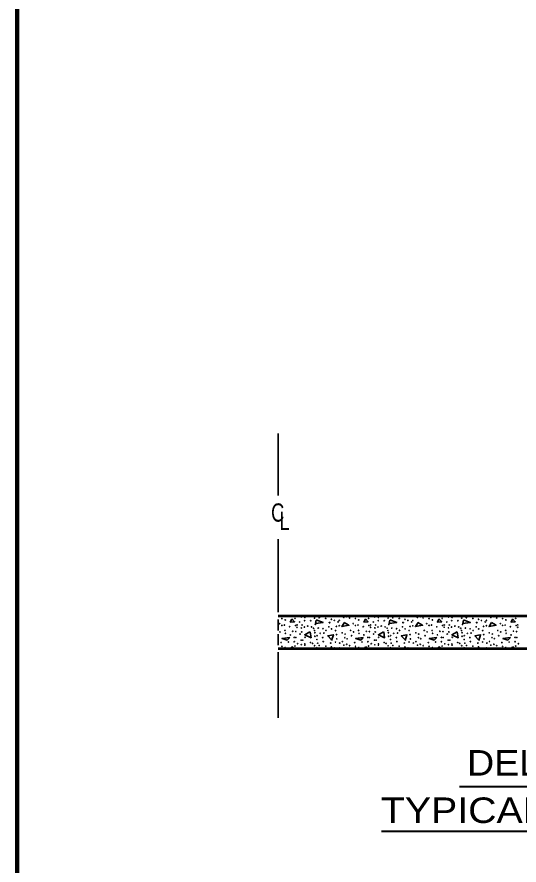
# Model space of a CAD drawing. Extents: x -89 to 766, y -60 to 484.
# Drawn here: x -31.9 to 50.6, y 91.5 to 231 of the extents above; entities that cross this region are included whole.
import ezdxf
from ezdxf.enums import TextEntityAlignment as Align

# ---------------------------------------------------------------- set-up
doc = ezdxf.new("R2010")
doc.units = 0
doc.header["$LTSCALE"] = 1.1
doc.layers.add('1', color=7, linetype='Continuous', lineweight=35)

msp = doc.modelspace()

# ---------------------------------------------------------------- linework, layer by layer
at = {"layer": '1'}
for p, q in [((11.028, 152.314), (11.028, 162.514)), ((11.028, 133.114), (11.028, 145.114)), ((11.028, 131.914), (11.028, 130.114)), ((11.028, 129.514), (11.028, 127.714)), ((13.138, 127.114), (13.287, 127.413)), ((13.287, 127.461), (13.617, 127.114)), ((17.291, 127.114), (17.319, 127.245)), ((17.319, 127.293), (17.763, 127.114)), ((25.234, 127.114), (25.383, 127.413)), ((25.383, 127.461), (25.713, 127.114)), ((29.387, 127.114), (29.415, 127.245)), ((29.415, 127.293), (29.859, 127.114)), ((37.33, 127.114), (37.479, 127.413)), ((37.479, 127.461), (37.809, 127.114)), ((41.483, 127.114), (41.511, 127.245)), ((41.511, 127.293), (41.955, 127.114)), ((49.426, 127.114), (49.575, 127.413)), ((49.575, 127.461), (49.905, 127.114)), ((11.028, 126.514), (11.028, 115.714))]:
    msp.add_line(p, q, dxfattribs=at)
at = {"layer": '1', "lineweight": 53}
for p, q in [((11.028, 132.514), (96.828, 132.514)), ((96.828, 127.114), (11.028, 127.114))]:
    msp.add_line(p, q, dxfattribs=at)
at = {"layer": '1', "lineweight": 40}
for p, q in [((40.868, 104.433), (122.541, 104.433)), ((28.02, 97.103), (136.478, 97.103))]:
    msp.add_line(p, q, dxfattribs=at)
at = {"layer": '1', "lineweight": 158}
msp.add_lwpolyline([(759.817, 478.083), (-31.883, 477.983), (-31.783, -48.017)], dxfattribs=at)
at = {"layer": '1'}
for points in [[(13.287, 132.021), (13.743, 131.541), (13.047, 131.493), (13.287, 131.973)], [(17.319, 131.853), (18.447, 131.397), (17.199, 131.253), (17.319, 131.805)], [(21.903, 131.397), (22.695, 130.965), (21.519, 130.749), (21.951, 131.421)], [(25.383, 132.021), (25.839, 131.541), (25.143, 131.493), (25.383, 131.973)], [(29.415, 131.853), (30.543, 131.397), (29.295, 131.253), (29.415, 131.805)], [(33.999, 131.397), (34.791, 130.965), (33.615, 130.749), (34.047, 131.421)], [(37.479, 132.021), (37.935, 131.541), (37.239, 131.493), (37.479, 131.973)], [(41.511, 131.853), (42.639, 131.397), (41.391, 131.253), (41.511, 131.805)], [(46.095, 131.397), (46.887, 130.965), (45.711, 130.749), (46.143, 131.421)], [(49.575, 132.021), (50.031, 131.541), (49.335, 131.493), (49.575, 131.973)], [(16.263, 129.885), (15.423, 129.405), (16.455, 128.901), (16.311, 129.909)], [(28.359, 129.885), (27.519, 129.405), (28.551, 128.901), (28.407, 129.909)], [(40.455, 129.885), (39.615, 129.405), (40.647, 128.901), (40.503, 129.909)], [(19.839, 128.445), (20.127, 129.405), (19.191, 129.213), (19.863, 128.493)], [(31.935, 128.445), (32.223, 129.405), (31.287, 129.213), (31.959, 128.493)], [(44.031, 128.445), (44.319, 129.405), (43.383, 129.213), (44.055, 128.493)]]:
    msp.add_lwpolyline(points, dxfattribs=at)
for points in [[(12.951, 128.949), (11.703, 128.805), (12.519, 128.517)], [(25.047, 128.949), (23.799, 128.805), (24.615, 128.517)], [(37.143, 128.949), (35.895, 128.805), (36.711, 128.517)], [(49.239, 128.949), (47.991, 128.805), (48.807, 128.517)]]:
    msp.add_lwpolyline(points, close=True, dxfattribs=at)
for centre in [(11.288, 131.231), (11.67, 132.058), (12.21, 131.851), (13.817, 132.106), (14.255, 132.482), (14.589, 131.501), (14.844, 132.329), (15.4, 131.724), (15.432, 132.466), (15.448, 132.265), (16.402, 131.708), (17.038, 132.154), (17.802, 132.201), (18.867, 132.09), (19.472, 131.406), (19.535, 131.406), (19.806, 131.963), (20.283, 131.772), (20.903, 131.517), (21.094, 131.772), (21.841, 132.249), (22.318, 132.402), (22.796, 132.169), (23.384, 131.231), (23.766, 132.058), (24.306, 131.851), (25.913, 132.106), (26.351, 132.482), (26.685, 131.501), (26.94, 132.329), (27.496, 131.724), (27.528, 132.466), (27.544, 132.265), (28.498, 131.708), (29.134, 132.154), (29.898, 132.201), (30.963, 132.09), (31.568, 131.406), (31.631, 131.406), (31.902, 131.963), (32.379, 131.772), (32.999, 131.517), (33.19, 131.772), (33.937, 132.249), (34.414, 132.402), (34.892, 132.169), (35.48, 131.231), (35.862, 132.058), (36.402, 131.851), (38.009, 132.106), (38.447, 132.482), (38.781, 131.501), (39.036, 132.329), (39.592, 131.724), (39.624, 132.466), (39.64, 132.265), (40.594, 131.708), (41.23, 132.154), (41.994, 132.201), (43.059, 132.09), (43.664, 131.406), (43.727, 131.406), (43.998, 131.963), (44.475, 131.772), (45.095, 131.517), (45.286, 131.772), (46.033, 132.249), (46.51, 132.402), (46.988, 132.169), (47.576, 131.231), (47.958, 132.058), (48.498, 131.851), (50.105, 132.106), (50.543, 132.482), (11.352, 129.863), (11.67, 130.945), (12.083, 130.992), (12.179, 130.117), (12.942, 130.722), (13.451, 129.99), (13.88, 130.929), (13.953, 129.926), (14.144, 130.642), (14.16, 131.024), (14.86, 130.531), (14.923, 129.863), (14.987, 131.008), (15.368, 130.658), (15.909, 130.833), (16.545, 130.69), (16.879, 130.483), (17.007, 130.101), (17.086, 129.735), (17.166, 131.088), (17.643, 130.499), (18.422, 130.388), (18.915, 130.117), (19.392, 130.706), (19.837, 130.372), (20.49, 130.085), (20.633, 130.77), (21.094, 130.881), (22.971, 130.117), (23.448, 129.863), (23.766, 130.945), (24.179, 130.992), (24.275, 130.117), (25.038, 130.722), (25.547, 129.99), (25.976, 130.929), (26.049, 129.926), (26.24, 130.642), (26.256, 131.024), (26.956, 130.531), (27.019, 129.863), (27.083, 131.008), (27.464, 130.658), (28.005, 130.833), (28.641, 130.69), (28.975, 130.483), (29.103, 130.101), (29.182, 129.735), (29.262, 131.088), (29.739, 130.499), (30.518, 130.388), (31.011, 130.117), (31.488, 130.706), (31.933, 130.372), (32.586, 130.085), (32.729, 130.77), (33.19, 130.881), (35.067, 130.117), (35.544, 129.863), (35.862, 130.945), (36.275, 130.992), (36.371, 130.117), (37.134, 130.722), (37.643, 129.99), (38.072, 130.929), (38.145, 129.926), (38.336, 130.642), (38.352, 131.024), (39.052, 130.531), (39.115, 129.863), (39.179, 131.008), (39.56, 130.658), (40.101, 130.833), (40.737, 130.69), (41.071, 130.483), (41.199, 130.101), (41.278, 129.735), (41.358, 131.088), (41.835, 130.499), (42.614, 130.388), (43.107, 130.117), (43.584, 130.706), (44.029, 130.372), (44.682, 130.085), (44.825, 130.77), (45.286, 130.881), (47.163, 130.117), (47.64, 129.863), (47.958, 130.945), (48.371, 130.992), (48.467, 130.117), (49.23, 130.722), (49.739, 129.99), (50.168, 130.929), (50.241, 129.926), (50.432, 130.642), (50.448, 131.024), (12.242, 129.64), (13.053, 129.37), (13.705, 128.972), (13.977, 128.953), (14.653, 129.513), (14.812, 128.51), (15.082, 128.51), (15.48, 128.988), (17.102, 129.163), (17.436, 128.622), (17.452, 129.242), (17.961, 129.64), (18.39, 128.94), (18.581, 129.672), (20.649, 129.433), (20.696, 128.717), (21.571, 129.72), (22.016, 128.924), (22.064, 129.513), (22.398, 128.749), (23.114, 129.242), (24.338, 129.64), (25.149, 129.37), (25.801, 128.972), (26.073, 128.953), (26.749, 129.513), (26.908, 128.51), (27.178, 128.51), (27.576, 128.988), (29.198, 129.163), (29.532, 128.622), (29.548, 129.242), (30.057, 129.64), (30.486, 128.94), (30.677, 129.672), (32.745, 129.433), (32.792, 128.717), (33.667, 129.72), (34.112, 128.924), (34.16, 129.513), (34.494, 128.749), (35.21, 129.242), (36.434, 129.64), (37.245, 129.37), (37.897, 128.972), (38.169, 128.953), (38.845, 129.513), (39.004, 128.51), (39.274, 128.51), (39.672, 128.988), (41.294, 129.163), (41.628, 128.622), (41.644, 129.242), (42.153, 129.64), (42.582, 128.94), (42.773, 129.672), (44.841, 129.433), (44.888, 128.717), (45.763, 129.72), (46.208, 128.924), (46.256, 129.513), (46.59, 128.749), (47.306, 129.242), (48.53, 129.64), (49.341, 129.37), (49.993, 128.972), (50.265, 128.953), (11.542, 128.113), (11.67, 127.498), (12.21, 127.291), (12.735, 128.208), (13.705, 128.256), (13.817, 127.546), (14.255, 127.922), (14.844, 127.769), (15.4, 127.164), (15.432, 127.906), (15.448, 127.705), (16.37, 128.129), (16.402, 127.148), (16.704, 127.985), (17.038, 127.594), (17.547, 128.017), (17.802, 127.641), (18.47, 128.288), (18.867, 127.53), (19.694, 128.033), (19.806, 127.403), (20.283, 127.212), (20.474, 128.208), (21.094, 127.212), (21.173, 128.033), (21.603, 128.272), (21.841, 127.689), (22.318, 127.842), (22.796, 127.609), (23.638, 128.113), (23.766, 127.498), (24.306, 127.291), (24.831, 128.208), (25.801, 128.256), (25.913, 127.546), (26.351, 127.922), (26.94, 127.769), (27.496, 127.164), (27.528, 127.906), (27.544, 127.705), (28.466, 128.129), (28.498, 127.148), (28.8, 127.985), (29.134, 127.594), (29.643, 128.017), (29.898, 127.641), (30.566, 128.288), (30.963, 127.53), (31.79, 128.033), (31.902, 127.403), (32.379, 127.212), (32.57, 128.208), (33.19, 127.212), (33.269, 128.033), (33.699, 128.272), (33.937, 127.689), (34.414, 127.842), (34.892, 127.609), (35.734, 128.113), (35.862, 127.498), (36.402, 127.291), (36.927, 128.208), (37.897, 128.256), (38.009, 127.546), (38.447, 127.922), (39.036, 127.769), (39.592, 127.164), (39.624, 127.906), (39.64, 127.705), (40.562, 128.129), (40.594, 127.148), (40.896, 127.985), (41.23, 127.594), (41.739, 128.017), (41.994, 127.641), (42.662, 128.288), (43.059, 127.53), (43.886, 128.033), (43.998, 127.403), (44.475, 127.212), (44.666, 128.208), (45.286, 127.212), (45.365, 128.033), (45.795, 128.272), (46.033, 127.689), (46.51, 127.842), (46.988, 127.609), (47.83, 128.113), (47.958, 127.498), (48.498, 127.291), (49.023, 128.208), (49.993, 128.256), (50.105, 127.546), (50.543, 127.922)]:
    msp.add_circle(centre, 0.0318, dxfattribs=at)
for centre, start, end in [((16.704, 132.545), 262.28656, 277.71344), ((28.8, 132.545), 262.28656, 277.71344), ((40.896, 132.545), 262.28656, 277.71344), ((11.018, 129.242), 289.58284, 70.41716)]:
    msp.add_arc(centre, 0.0318, start, end, dxfattribs=at)

# ---------------------------------------------------------------- texts
at = {"layer": '1', "width": 0.75}
for s, p in [('C', (9.891, 148.015)), ('L', (11.248, 146.657))]:
    msp.add_text(s, height=3, dxfattribs=at).set_placement(p)
at = {"layer": '1'}
for s, width, p in [('DELINEATOR PLACEMENT', 1.1, (81.578, 106.233)), ('TYPICAL SECTION WITH CURBING', 1.15, (81.578, 98.433))]:
    msp.add_text(s, height=4.2, dxfattribs=dict(at, width=width)).set_placement(p, align=Align.CENTER)

doc.saveas('drawing.dxf')
